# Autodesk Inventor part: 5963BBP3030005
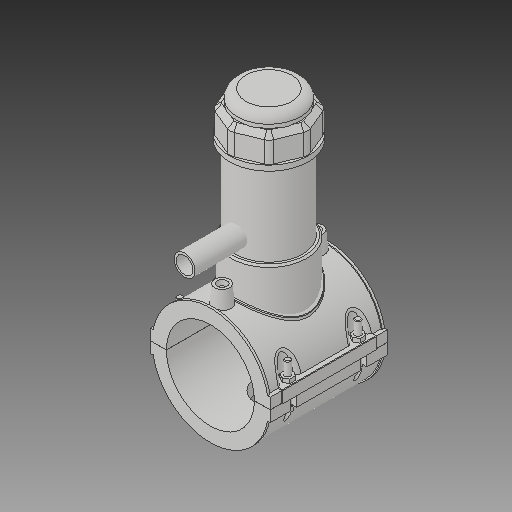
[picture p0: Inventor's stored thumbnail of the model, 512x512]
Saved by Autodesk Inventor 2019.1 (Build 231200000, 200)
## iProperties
Created: 2017-07
Part Number: 5963BBP3030005
Material: Generic
Description: PLASSON TAPPING SADDLE 3''IPS x 1/2''IPS
Document SubType Name: Modeling
Designer: KIM
Density: 1 g/cm^3
Appearance: Default
Author: KIM
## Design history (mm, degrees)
derived "5963BBP_5963BUP.ipt"
feature "Solid1::5963BBP_5963BUP.ipt"
feature "Solid2::5963BBP_5963BUP.ipt"
feature "Solid3::5963BBP_5963BUP.ipt"
tag "TaggingFeature1"
body "Solid1"
body "Solid2"
body "Solid3"
other parameters: "d0" = 88.7, "d2" = 120.904, "d3" = 22.175, "d4" = 118.11, "d5" = 0, "d6" = 0.1, "d8" = 0, "d19" = 6, "d20" = 6, "d21" = 70.866, "d23" = 0, "d24" = 35.433, "d26" = 0, "d27" = 3, "d28" = 3, "d29" = 3, "d30" = 29.56667, "d31" = 6, "d32" = 0, "d33" = 0, "d34" = 0.6, "d40" = 59.9612, "d41" = 79.83, "d43" = 0, "d45" = 0, "d47" = 128.521, "d70" = 15, "d72" = 0, "d73" = 6, "d75" = 5, "d76" = 0, "d77" = 4.435, "d78" = 74.35, "d79" = 15, "d80" = 47.244, "d82" = 5 deg, "d84" = 4, "d85" = 14, "d86" = 0, "d87" = 3, "d88" = 0, "d89" = 1, "d90" = 1, "d91" = 94.488, "d92" = 0, "d93" = 0.5, "d94" = 46.68421, "d96" = 117.6162, "d97" = 2.3622, "d98" = 0, "d102" = 0.887, "d120" = 140 deg, "d121" = 24.228, "d122" = 20 deg, "d123" = 230.62, "d124" = 69.186, "d126" = 0, "d143" = 91.361, "d145" = 20.46923, "d149" = 1.3305, "d150" = 22.51615, "d153" = 118.11, "d154" = 0, "d156" = 57.655, "d157" = 160 deg, "d159" = 5.322, "d161" = 1.3305, "d162" = 70.866, "d163" = 0, "d164" = 44.35, "d167" = 8.87, "d168" = 56.24878, "d170" = 3.2805, "d172" = 0, "d173" = 1, "d175" = 44.35, "d176" = 20 deg, "d177" = 6.209, "d178" = 26.61, "d180" = 0, "d183" = 10.644, "d184" = 4.9672, "d185" = 38.38575, "d186" = 38.38575, "d187" = 57.655, "d188" = 7.983, "d189" = 6.209, "d190" = 0, "d191" = 86.4825, "d193" = 6.9984, "d194" = 4.13385, "d195" = 90 deg, "d197" = 0, "d199" = 0, "d200" = 13.305, "d202" = 0, "d203" = 177.038, "d204" = 75.8385, "d205" = 55.881, "d206" = 67.8555, "d207" = 132.7785, "d208" = 138.08964, "d209" = 164.64534, "d210" = 68.6538, "d211" = 79.83, "d212" = 63.864, "d213" = 48.9816, "d216" = 0, "d217" = 8.87, "d218" = 8.87, "d219" = 1.774, "d222" = 88.7, "d224" = 0, "d225" = 65.024, "d226" = 21.2, "d227" = 16.96, "d228" = 85.09, "d230" = 5.322, "d_" = 88.7, "B_" = 120.904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
